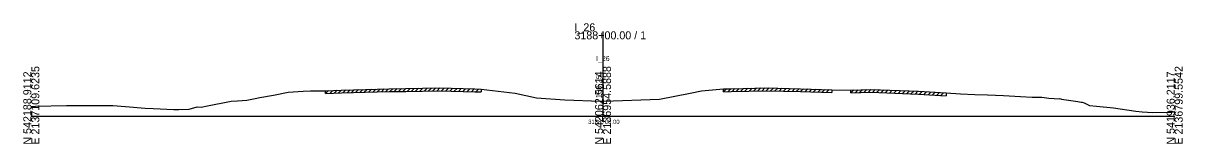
# Model space of a CAD drawing. Extents: x -13101 to 4803, y -924 to 22390.
# Drawn here: x 997.2 to 1402.8, y 13990.3 to 14032.5 of the extents above; entities that cross this region are included whole.
import ezdxf

# ---------------------------------------------------------------- set-up
doc = ezdxf.new("R2010")
doc.units = 0
for name, color, linetype in [('RD_GPK_XS_Cell', 7, 'Continuous'), ('RD_XS_ExGround', 7, 'Continuous'), ('RD_XS_ExPaveRet', 7, 'Continuous'), ('RD_XS_TX_Baseline', 7, 'Continuous'), ('RD_XS_TX_Elev_EX', 7, 'Continuous'), ('RD_XS_TX_Station', 7, 'Continuous')]:
    doc.layers.add(name, color=color, linetype=linetype)

msp = doc.modelspace()

# ---------------------------------------------------------------- linework, layer by layer
at = {"layer": 'RD_GPK_XS_Cell'}
for p, q in [((1200, 14000), (1200, 14029.63)), ((1000, 14000), (1200, 14000)), ((1200, 14000), (1400, 14000))]:
    msp.add_line(p, q, dxfattribs=at)
at = {"layer": 'RD_XS_ExGround'}
msp.add_lwpolyline([(1000, 14003.36), (1001.49, 14003.43), (1012.28, 14003.67), (1024.69, 14003.68), (1028.48, 14003.64), (1032.94, 14003.32), (1039.86, 14002.79), (1042.68, 14002.67), (1049.87, 14002.26), (1051.61, 14002.27), (1055.24, 14002.47), (1057.97, 14003.18), (1059.45, 14003.12), (1060.03, 14003.21), (1061.04, 14003.42), (1069.89, 14005.22), (1072.13, 14005.36), (1075.4, 14005.52), (1078.26, 14006.17), (1079.89, 14006.47), (1084.74, 14007.36), (1089.9, 14008.34), (1095.06, 14008.66), (1097.65, 14008.8), (1102.96, 14008.88), (1108.55, 14009.11), (1125.14, 14009.54), (1131, 14009.64), (1142.78, 14009.87), (1155.12, 14009.47), (1157.39, 14009.42), (1169.31, 14007.96), (1176.76, 14006.42), (1186.63, 14005.73), (1199.07, 14005.26), (1200.25, 14005.24), (1219.73, 14005.97), (1230.45, 14008.04), (1234.46, 14008.79), (1242.13, 14009.47), (1244.8, 14009.56), (1257.15, 14009.88), (1269.09, 14009.57), (1280.01, 14009.21), (1286.73, 14009.1), (1293.69, 14009.32), (1310.34, 14008.66), (1320, 14008.11), (1325.05, 14007.83), (1330.12, 14007.58), (1334.47, 14007.38), (1340.13, 14007.18), (1346.11, 14006.84), (1350.14, 14006.65), (1351.74, 14006.63), (1353.53, 14006.57), (1355.92, 14006.22), (1359.72, 14005.98), (1359.9, 14006.15), (1360.39, 14005.86), (1366.11, 14005.06), (1367.26, 14004.91), (1367.59, 14004.87), (1368.28, 14004.59), (1370.16, 14003.66), (1372.61, 14003.42), (1378.61, 14002.89), (1386.35, 14001.76), (1388.61, 14001.47), (1392.32, 14001.26), (1398.1, 14001.33), (1398.62, 14001.33), (1399.49, 14001.52), (1400, 14001.58)], dxfattribs=at)
at = {"layer": 'RD_XS_ExPaveRet'}
for p, q in [((1102.96, 14007.88), (1104.01, 14008.93)), ((1102.96, 14007.88), (1102.96, 14008.88)), ((1104.46, 14007.94), (1105.51, 14008.99)), ((1105.96, 14008), (1107.01, 14009.05)), ((1107.46, 14008.07), (1108.51, 14009.11)), ((1108.55, 14008.11), (1125.14, 14008.54)), ((1108.96, 14008.12), (1109.99, 14009.15)), ((1110.46, 14008.16), (1111.49, 14009.19)), ((1111.96, 14008.2), (1112.99, 14009.23)), ((1113.46, 14008.24), (1114.49, 14009.26)), ((1114.96, 14008.28), (1115.99, 14009.3)), ((1116.46, 14008.32), (1117.49, 14009.34)), ((1117.96, 14008.36), (1118.99, 14009.38)), ((1119.46, 14008.39), (1120.49, 14009.42)), ((1120.96, 14008.43), (1121.99, 14009.46)), ((1122.46, 14008.47), (1123.49, 14009.5)), ((1123.96, 14008.51), (1124.99, 14009.54)), ((1125.14, 14008.54), (1131, 14008.64)), ((1125.46, 14008.55), (1126.48, 14009.57)), ((1126.96, 14008.57), (1127.98, 14009.59)), ((1128.46, 14008.6), (1129.48, 14009.61)), ((1129.96, 14008.62), (1130.98, 14009.64)), ((1131, 14008.64), (1142.78, 14008.87)), ((1131.46, 14008.65), (1132.48, 14009.67)), ((1132.96, 14008.68), (1133.98, 14009.7)), ((1134.46, 14008.71), (1135.48, 14009.73)), ((1135.96, 14008.73), (1136.98, 14009.75)), ((1137.46, 14008.76), (1138.48, 14009.78)), ((1138.96, 14008.79), (1139.98, 14009.81)), ((1140.46, 14008.82), (1141.48, 14009.84)), ((1141.96, 14008.85), (1142.97, 14009.86)), ((1142.78, 14008.87), (1155.12, 14008.47)), ((1143.46, 14008.84), (1144.43, 14009.81)), ((1144.96, 14008.8), (1145.93, 14009.76)), ((1146.46, 14008.75), (1147.43, 14009.72)), ((1147.96, 14008.7), (1148.93, 14009.67)), ((1149.46, 14008.65), (1150.43, 14009.62)), ((1150.96, 14008.6), (1151.93, 14009.57)), ((1152.46, 14008.56), (1153.43, 14009.52)), ((1153.96, 14008.51), (1154.93, 14009.48)), ((1155.12, 14008.47), (1157.39, 14008.42)), ((1155.46, 14008.46), (1156.44, 14009.44)), ((1157.39, 14009.42), (1157.39, 14008.42)), ((1242.13, 14008.47), (1243.17, 14009.5)), ((1242.13, 14008.47), (1242.13, 14009.47)), ((1242.13, 14008.47), (1244.8, 14008.56)), ((1243.63, 14008.52), (1244.67, 14009.55)), ((1244.8, 14008.56), (1257.15, 14008.88)), ((1245.13, 14008.56), (1246.16, 14009.59)), ((1246.63, 14008.6), (1247.66, 14009.63)), ((1248.13, 14008.64), (1249.16, 14009.67)), ((1249.63, 14008.68), (1250.66, 14009.71)), ((1251.13, 14008.72), (1252.16, 14009.75)), ((1252.63, 14008.76), (1253.66, 14009.79)), ((1254.13, 14008.8), (1255.16, 14009.83)), ((1255.63, 14008.84), (1256.66, 14009.86)), ((1257.13, 14008.88), (1258.11, 14009.85)), ((1257.15, 14008.88), (1269.09, 14008.57)), ((1258.63, 14008.84), (1259.61, 14009.81)), ((1260.13, 14008.8), (1261.11, 14009.77)), ((1261.63, 14008.76), (1262.61, 14009.73)), ((1263.13, 14008.72), (1264.11, 14009.7)), ((1264.63, 14008.68), (1265.61, 14009.66)), ((1266.13, 14008.64), (1267.11, 14009.62)), ((1267.63, 14008.6), (1268.61, 14009.58)), ((1269.09, 14008.57), (1280.01, 14008.21)), ((1269.13, 14008.56), (1270.1, 14009.53)), ((1270.63, 14008.52), (1271.6, 14009.48)), ((1272.13, 14008.47), (1273.1, 14009.44)), ((1273.63, 14008.42), (1274.6, 14009.39)), ((1275.13, 14008.37), (1276.1, 14009.34)), ((1276.63, 14008.32), (1277.6, 14009.29)), ((1278.13, 14008.27), (1279.1, 14009.24)), ((1280.01, 14009.21), (1280.01, 14008.21)), ((1286.73, 14008.1), (1287.76, 14009.14)), ((1286.73, 14008.1), (1286.73, 14009.1)), ((1286.73, 14008.1), (1293.69, 14008.32)), ((1288.23, 14008.15), (1289.26, 14009.18)), ((1289.73, 14008.2), (1290.76, 14009.23)), ((1291.23, 14008.25), (1292.26, 14009.28)), ((1292.73, 14008.29), (1293.75, 14009.32)), ((1293.69, 14008.32), (1310.34, 14007.66)), ((1294.23, 14008.3), (1295.19, 14009.26)), ((1295.73, 14008.24), (1296.69, 14009.2)), ((1297.23, 14008.18), (1298.19, 14009.15)), ((1298.73, 14008.12), (1299.69, 14009.09)), ((1300.23, 14008.06), (1301.19, 14009.03)), ((1301.73, 14008), (1302.69, 14008.97)), ((1303.23, 14007.95), (1304.19, 14008.91)), ((1304.73, 14007.89), (1305.69, 14008.85)), ((1306.23, 14007.83), (1307.19, 14008.79)), ((1307.73, 14007.77), (1308.69, 14008.73)), ((1309.23, 14007.71), (1310.19, 14008.67)), ((1310.73, 14007.64), (1311.67, 14008.59)), ((1312.23, 14007.56), (1313.17, 14008.5)), ((1313.73, 14007.47), (1314.67, 14008.41)), ((1315.23, 14007.38), (1316.17, 14008.33)), ((1316.73, 14007.3), (1317.67, 14008.24)), ((1102.96, 14007.88), (1108.55, 14008.11)), ((1310.34, 14007.66), (1320, 14007.11)), ((1318.23, 14007.21), (1319.17, 14008.16)), ((1320, 14008.11), (1320, 14007.11))]:
    msp.add_line(p, q, dxfattribs=at)

# ---------------------------------------------------------------- texts
at = {"layer": 'RD_GPK_XS_Cell'}
for s, p in [('3188+00.00 / 1', (1190, 14026.83)), ('I_26', (1190, 14029.63))]:
    msp.add_text(s, height=2.8, dxfattribs=at).set_placement(p)
for s, p in [('E 2137109.6235', (1002.8, 13990)), ('E 2136954.5888', (1202.8, 13990)), ('E 2136799.5542', (1402.8, 13990)), ('N 542188.9112', (1000, 13990)), ('N 542062.5614', (1200, 13990)), ('N 541936.2117', (1400, 13990))]:
    msp.add_text(s, height=2.8, rotation=90, dxfattribs=at).set_placement(p)
at = {"layer": 'RD_XS_TX_Baseline'}
msp.add_text('I_26', height=1.75, dxfattribs=at).set_placement((1197.6, 14019.25))
at = {"layer": 'RD_XS_TX_Elev_EX'}
msp.add_text('100.25', height=2, rotation=90, dxfattribs=at).set_placement((1199.5, 14006.25))
at = {"layer": 'RD_XS_TX_Station'}
msp.add_text('3188+00.00', height=1.5, dxfattribs=at).set_placement((1194.81, 13997.25))

doc.saveas('drawing.dxf')
